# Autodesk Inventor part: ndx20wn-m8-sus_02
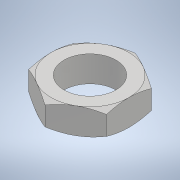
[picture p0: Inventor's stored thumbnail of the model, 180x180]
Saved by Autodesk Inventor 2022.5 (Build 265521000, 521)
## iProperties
Part Number: ndx20wn-m8-sus_02
Material: 一般
Document SubType Name: Modeling
Designer: ImaoCorp
Density: 1 g/cm^3
Appearance: 既定
Author: ImaoCorp
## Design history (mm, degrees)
feature "ndx20wn-m8-sus_02"
node "ソリッド1"
